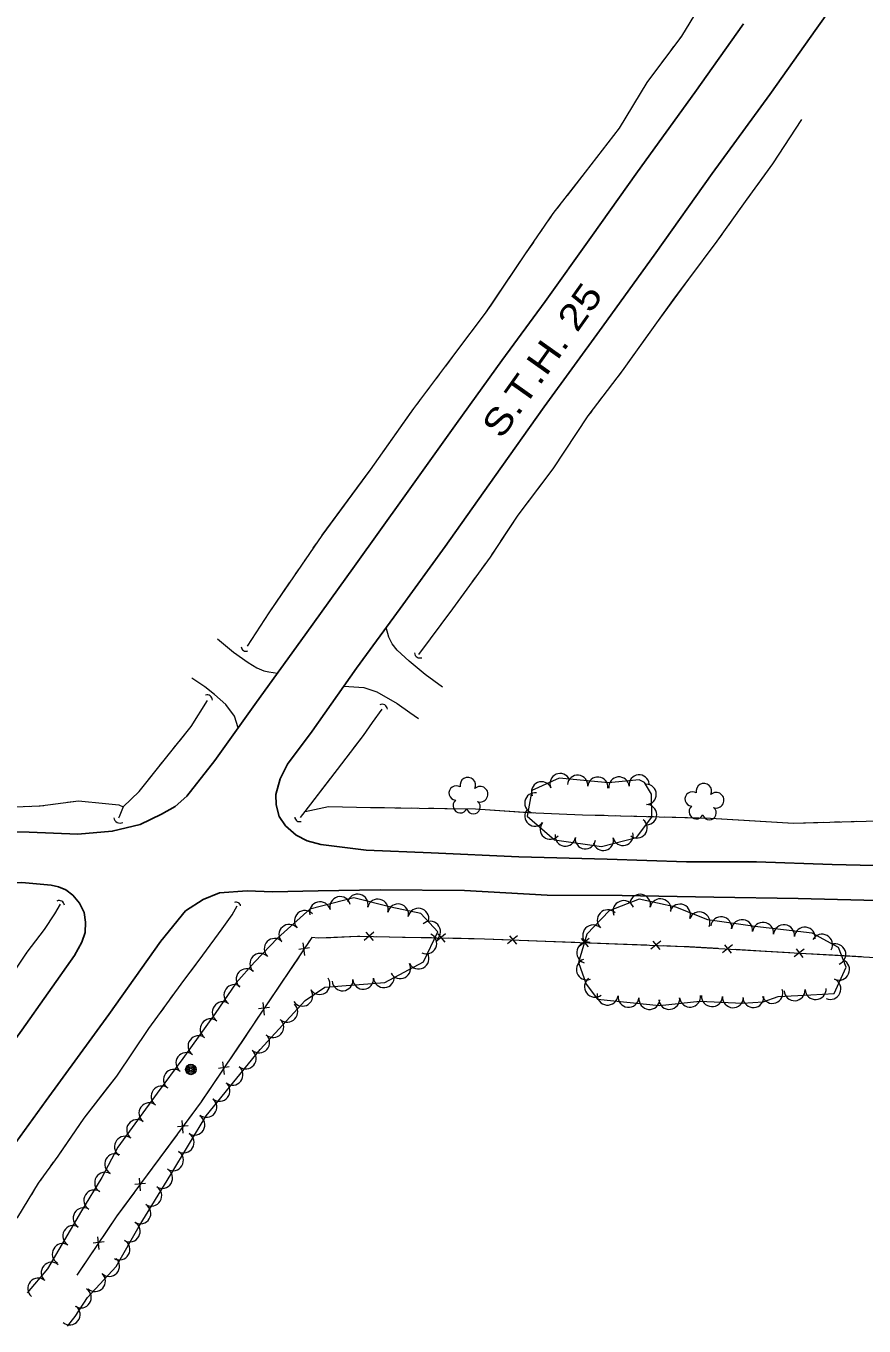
# Model space of a CAD drawing. Extents: x 298072 to 300359, y 47756 to 50122.
# Drawn here: x 299060 to 299380.3, y 48326.9 to 48823.7 of the extents above; entities that cross this region are included whole.
import ezdxf

# ---------------------------------------------------------------- set-up
doc = ezdxf.new("R2010")
doc.units = 0
doc.header["$LTSCALE"] = 2.4
doc.linetypes.add('LONG_DASHED', pattern=[7.5, 6, -1.5])
for name, color, linetype, lineweight in [('11', 7, 'Continuous', 25), ('14', 7, 'Continuous', 13), ('15', 7, 'Continuous', 13), ('17', 7, 'LONG_DASHED', 13), ('18', 7, 'Continuous', 13), ('19', 7, 'Continuous', 13)]:
    doc.layers.add(name, color=color, linetype=linetype, lineweight=lineweight)

msp = doc.modelspace()

# ---------------------------------------------------------------- linework, layer by layer
at = {"layer": '11'}
for points in [[(299159.9, 48541.54), (299169.315, 48554.227), (299186.27, 48578.226), (299202.993, 48601.032), (299220.126, 48624.785), (299239.084, 48651.357), (299258.045, 48678.115), (299280.157, 48708.592), (299300.706, 48737.003), (299322.267, 48767.276), (299344.231, 48797.56), (299362.207, 48822.854), (299379.626, 48847.266)], [(299040.651, 48515.988), (299061.171, 48515.642), (299079.772, 48514.891), (299092.916, 48515.978), (299103.646, 48518.533), (299111.803, 48522.431), (299117.044, 48525.433), (299121.494, 48529.393), (299132.182, 48543.024), (299148.033, 48565.259), (299166.727, 48590.963), (299185.573, 48617.31), (299204.756, 48644.113), (299224.578, 48671.815), (299241.848, 48695.801), (299258.384, 48718.46), (299275.868, 48742.919), (299293.681, 48768), (299315.556, 48798.256), (299334.267, 48824.557)], [(299159.9, 48541.54), (299157.116, 48536.015), (299155.509, 48530.063), (299155.644, 48525.997), (299156.743, 48521.651), (299159.162, 48518.027), (299163.236, 48514.452), (299167.446, 48512.314), (299172.654, 48510.945), (299189.998, 48508.773), (299214.809, 48507.751), (299248.337, 48506.161), (299282.112, 48505.341), (299312.382, 48504.318), (299339.159, 48504.234), (299368.13, 48503.278), (299410.735, 48502.254), (299439.997, 48501.987), (299472.691, 48501.745), (299499.707, 48501.466), (299530.639, 48500.816), (299559.37, 48500.568), (299584.941, 48499.652), (299594.667, 48499.415)], [(298856.43, 48502.098), (298886.422, 48502.837), (298921.67, 48501.855), (298960.034, 48500.114), (299004.015, 48497.993), (299038.664, 48495.79), (299058.368, 48496.338), (299069.567, 48495.309), (299072.437, 48494.733), (299075.152, 48493.629), (299077.868, 48491.528), (299080.463, 48488.49), (299082.145, 48484.904), (299082.73, 48481.177), (299082.533, 48477.203), (299081.364, 48473.612), (299078.474, 48468.424), (299058.337, 48439.986), (299037.794, 48411.569), (299021.737, 48389.305), (299009.962, 48373.031)], [(299028.794, 48358.922), (299046.078, 48383.296), (299067.642, 48413.073), (299091.651, 48445.959), (299111.467, 48473.957), (299120.982, 48485.542), (299127.672, 48489.835), (299133.956, 48492.451), (299144.552, 48493.154), (299154.25, 48492.804), (299171.68, 48493.142), (299195.394, 48493.553), (299227.514, 48493.295), (299259.174, 48491.522), (299287.804, 48491.45), (299322.814, 48490.828), (299355.076, 48490.314), (299380.259, 48489.565), (299413.071, 48489.188)]]:
    msp.add_lwpolyline(points, dxfattribs=at)
at = {"layer": '14'}
for centre, radius in [((299122.993, 48424.924), 2.018), ((299122.981, 48424.929), 1.518), ((299123.017, 48424.911), 1.008), ((299123.011, 48424.92), 0.502)]:
    msp.add_circle(centre, radius, dxfattribs=at)
at = {"layer": '15'}
for p, q in [((299192.966, 48477.353), (299189.243, 48474.242)), ((299192.732, 48474.17), (299190.046, 48477.347)), ((299165.783, 48473.273), (299166.382, 48468.458)), ((299203.867, 48475.416), (299194.072, 48475.619)), ((299215.005, 48475.185), (299203.867, 48475.416)), ((299220.375, 48476.785), (299216.652, 48473.674)), ((299220.142, 48473.602), (299217.456, 48476.779)), ((299231.277, 48474.848), (299221.481, 48475.051)), ((299247.808, 48475.998), (299244.031, 48472.953)), ((299247.519, 48472.819), (299244.889, 48476.042)), ((299258.674, 48473.87), (299248.883, 48474.244)), ((299269.806, 48473.445), (299258.674, 48473.87)), ((299275.203, 48474.951), (299271.426, 48471.906)), ((299274.914, 48471.772), (299272.284, 48474.996)), ((299286.069, 48472.823), (299276.278, 48473.197)), ((299297.201, 48472.398), (299286.069, 48472.823)), ((299302.598, 48473.904), (299298.822, 48470.859)), ((299302.309, 48470.726), (299299.679, 48473.949)), ((299330.01, 48472.496), (299326.174, 48469.526)), ((299329.659, 48469.324), (299327.092, 48472.598)), ((299164.22, 48467.892), (299157.994, 48458.654)), ((299168.332, 48471.353), (299164.207, 48470.815)), ((299324.584, 48471.096), (299313.463, 48471.74)), ((299340.832, 48470.156), (299331.05, 48470.722)), ((299351.954, 48469.512), (299340.832, 48470.156)), ((299357.379, 48470.912), (299353.544, 48467.942)), ((299357.028, 48467.74), (299354.462, 48471.014)), ((299368.202, 48468.572), (299358.42, 48469.138)), ((299379.323, 48467.928), (299368.202, 48468.572)), ((299157.994, 48458.654), (299152.519, 48450.528)), ((299153.011, 48448.618), (299148.886, 48448.08)), ((299150.462, 48450.538), (299151.061, 48445.724)), ((299148.899, 48445.157), (299142.673, 48435.919)), ((299142.673, 48435.919), (299137.198, 48427.794)), ((299135.141, 48427.804), (299135.74, 48422.989)), ((299137.69, 48425.884), (299133.565, 48425.346)), ((299133.578, 48422.423), (299127.352, 48413.185)), ((299121.967, 48403.355), (299117.822, 48402.997)), ((299119.502, 48405.384), (299119.892, 48400.548)), ((299117.708, 48400.076), (299111.089, 48391.115)), ((299111.089, 48391.115), (299105.267, 48383.235)), ((299103.212, 48383.334), (299103.602, 48378.498)), ((299101.418, 48378.025), (299094.798, 48369.065)), ((299105.676, 48381.305), (299101.531, 48380.946)), ((299089.803, 48359.037), (299085.678, 48358.502)), ((299087.255, 48360.959), (299087.85, 48356.144)), ((299085.688, 48355.579), (299079.456, 48346.345))]:
    msp.add_line(p, q, dxfattribs=at)
for points in [[(299395.571, 48466.988), (299311.592, 48471.848), (299235.229, 48474.766), (299186.719, 48475.771), (299171.675, 48475.059), (299169.284, 48475.406), (299126.928, 48412.555), (299094.716, 48368.954), (299079.456, 48346.345)], [(299176.467, 48475.286), (299171.675, 48475.059), (299169.284, 48475.406), (299167.84, 48473.263)], [(299187.596, 48475.753), (299186.719, 48475.771), (299176.467, 48475.286)], [(299242.411, 48474.492), (299235.229, 48474.766), (299231.277, 48474.848)], [(299313.463, 48471.74), (299311.592, 48471.848), (299303.674, 48472.151)], [(299127.352, 48413.185), (299126.928, 48412.555), (299121.557, 48405.285)], [(299094.798, 48369.065), (299094.716, 48368.954), (299089.312, 48360.947)]]:
    msp.add_lwpolyline(points, dxfattribs=at)
for centre, radius, start, end in [((299144.134, 48586.606), 1.876, 184.1637, 290.40327), ((299210.562, 48584.246), 2.092, 183.95389, 290.19346), ((299129.197, 48566.037), 2.046, 0.76582, 107.00538), ((299196.062, 48562.335), 2.127, 8.59007, 114.82964), ((299095.918, 48521.516), 2.445, 190.58294, 296.8225), ((299164.504, 48521.45), 1.825, 183.7445, 289.98407), ((299072.647, 48487.387), 2.095, 8.09709, 114.33665), ((299140.39, 48487.219), 1.627, 7.79274, 114.03231)]:
    msp.add_arc(centre, radius, start, end, dxfattribs=at)
at = {"layer": '17'}
for points in [[(299219.116, 48571.015), (299212.518, 48575.834), (299206.424, 48580.906), (299201.79, 48585.159), (299199.885, 48587.62), (299198.604, 48590.08), (299197.672, 48593.775)], [(299133.119, 48589.509), (299139.311, 48584.442), (299144.858, 48580.479), (299148.204, 48578.47), (299150.908, 48577.301), (299152.746, 48576.932), (299156.137, 48576.402)], [(299141.099, 48555.532), (299139.61, 48559.903), (299136.324, 48564.36), (299132.014, 48568.274), (299128.347, 48571.126), (299123.408, 48574.45)], [(299181.427, 48571.371), (299189.105, 48570.879), (299194.064, 48569.185), (299201.82, 48564.793), (299206.717, 48561.367), (299210.011, 48559.055)]]:
    msp.add_lwpolyline(points, dxfattribs=at)
at = {"layer": '18'}
for points in [[(299282.566, 48534.477), (299263.708, 48536.197), (299253.272, 48531.579), (299251.49, 48521.681), (299262.008, 48512.675), (299279.9, 48510.172), (299293.268, 48513.624), (299299.235, 48521.33), (299299.044, 48530.132), (299296.374, 48534.579), (299294.312, 48535.664)], [(299302.043, 48449.378), (299317.569, 48451.066), (299333.857, 48450.26), (299341.674, 48450.736), (299347.511, 48452.77), (299360.005, 48453.458), (299368.909, 48453.948), (299373.444, 48464.01), (299370.573, 48471.493), (299360.506, 48477.058), (299338.564, 48479.616), (299320.595, 48482.046), (299308.331, 48487.001), (299294.354, 48490.065), (299282.854, 48485.5), (299274.306, 48476.571), (299271.193, 48465.803), (299274.109, 48457.508), (299278.375, 48451.82)]]:
    msp.add_lwpolyline(points, close=True, dxfattribs=at)
msp.add_lwpolyline([(299075.868, 48326.889), (299078.715, 48330.487), (299083.47, 48337.821), (299094.439, 48349.661), (299103.168, 48365.018), (299115.294, 48384.758), (299128.814, 48407.143), (299149.428, 48432.491), (299166.683, 48451.318), (299174.152, 48456.349), (299197.082, 48458.109), (299211.942, 48465.998), (299217.362, 48477.464), (299210.935, 48484.466), (299199.381, 48486.922), (299185.319, 48490.47), (299168.428, 48486.194), (299156.181, 48475.214), (299147.271, 48465.98), (299140.245, 48458.02), (299132.32, 48446.358), (299119.928, 48429.108), (299110.122, 48415.851), (299095.071, 48395.266), (299088.949, 48383.579), (299081.159, 48370.859), (299068.236, 48348.697), (299060.478, 48339.538)], dxfattribs=at)
for centre, radius, start, end in [((299264.127, 48534.165), 3.875, 23.87737, 203.86205), ((299270.805, 48533.513), 3.875, 354.79625, 174.78093), ((299294.335, 48533.628), 3.875, 5.77814, 185.76281), ((299224.418, 48530.576), 2.777, 55.8556, 263.62859), ((299228.861, 48533.6), 2.974, 332.88471, 194.11859), ((299233.559, 48530.107), 2.975, 250.53553, 133.5088), ((299257.04, 48531.028), 3.875, 23.87737, 203.86205), ((299278.522, 48532.809), 3.875, 354.79625, 174.78093), ((299286.625, 48532.848), 3.875, 5.77814, 185.76281), ((299297.017, 48530.037), 3.875, 271.25076, 91.23544), ((299319.068, 48531.308), 2.974, 332.88471, 194.11859), ((299225.991, 48525.765), 2.783, 132.53262, 333.54366), ((299231.002, 48525.212), 2.611, 195.24076, 53.17337), ((299254.466, 48526.765), 3.875, 79.80167, 259.78635), ((299314.625, 48528.284), 2.777, 55.8556, 263.62859), ((299323.766, 48527.815), 2.975, 250.53553, 133.5088), ((299254.495, 48521.778), 3.875, 139.43599, 319.42067), ((299297.185, 48522.289), 3.875, 271.25076, 91.23544), ((299316.198, 48523.473), 2.783, 132.53262, 333.54366), ((299321.209, 48522.92), 2.611, 195.24076, 53.17337), ((299260.382, 48516.738), 3.875, 139.43599, 319.42067), ((299293.5, 48517.237), 3.875, 232.25591, 52.24059), ((299266.124, 48514.147), 3.875, 172.04396, 352.02863), ((299273.799, 48513.074), 3.875, 172.04396, 352.02863), ((299280.657, 48512.462), 3.875, 194.48677, 14.47145), ((299288.161, 48514.4), 3.875, 194.48677, 14.47145), ((299172.355, 48485.045), 3.969, 14.21378, 194.19846), ((299180.049, 48486.993), 3.969, 14.21378, 194.19846), ((299186.726, 48487.973), 3.969, 345.84685, 165.83153), ((299194.421, 48486.031), 3.969, 345.84685, 165.83153), ((299202.222, 48484.194), 3.969, 348.00709, 167.99176), ((299288.378, 48485.428), 4.022, 21.65859, 201.64326), ((299294.664, 48487.842), 4.022, 347.64303, 167.6277), ((299302.521, 48486.119), 4.022, 347.64303, 167.6277), ((299309.914, 48484.091), 4.022, 338.00757, 157.99225), ((299166.529, 48481.702), 3.969, 41.88535, 221.87003), ((299209.986, 48482.544), 3.969, 348.00709, 167.99176), ((299282.344, 48481.923), 4.022, 46.25652, 226.24119), ((299317.372, 48481.077), 4.022, 338.00757, 157.99225), ((299325.683, 48479.233), 4.022, 352.30611, 172.29079), ((299160.62, 48476.404), 3.969, 41.88535, 221.87003), ((299214.414, 48477.604), 3.969, 312.55588, 132.54056), ((299276.781, 48476.112), 4.022, 46.25652, 226.24119), ((299333.654, 48478.155), 4.022, 352.30611, 172.29079), ((299341.672, 48477.134), 4.022, 353.35813, 173.34281), ((299349.662, 48476.203), 4.022, 353.35813, 173.34281), ((299357.652, 48475.271), 4.022, 353.35813, 173.34281), ((299155.011, 48471.01), 3.969, 46.03069, 226.01537), ((299212.988, 48473.072), 3.969, 244.70747, 64.69215), ((299274.478, 48469.585), 4.022, 73.88322, 253.8679), ((299364.227, 48472.595), 4.022, 331.07401, 151.05869), ((299369.308, 48468.912), 4.022, 290.99795, 110.98263), ((299149.5, 48465.298), 3.969, 46.03069, 226.01537), ((299210.001, 48467.319), 3.969, 207.97097, 27.95565), ((299144.275, 48459.447), 3.969, 48.574, 228.55868), ((299202.991, 48463.598), 3.969, 207.97097, 27.95565), ((299274.339, 48463.201), 4.022, 109.37613, 289.36081), ((299370.708, 48463.064), 4.022, 245.74631, 65.73098), ((299172.197, 48457.537), 3.969, 213.97124, 33.95592), ((299180.951, 48458.954), 3.969, 184.39681, 4.38149), ((299188.865, 48459.562), 3.969, 184.39681, 4.38149), ((299196.779, 48460.169), 3.969, 184.39681, 4.38149), ((299277.443, 48456.571), 4.022, 126.87756, 306.86224), ((299367.403, 48455.731), 4.022, 245.74631, 65.73098), ((299139.603, 48453.379), 3.969, 55.8093, 235.79398), ((299165.614, 48453.103), 3.969, 213.97124, 33.95592), ((299282.256, 48453.536), 4.022, 174.11688, 354.10156), ((299290.257, 48452.711), 4.022, 174.11688, 354.10156), ((299313.811, 48452.775), 4.022, 186.21254, 6.19721), ((299322.161, 48452.947), 4.022, 177.17473, 357.15941), ((299330.195, 48452.549), 4.022, 177.17473, 357.15941), ((299337.994, 48452.621), 4.022, 183.49227, 3.47694), ((299345.217, 48454.2), 4.022, 199.21941, 19.20408), ((299353.734, 48455.221), 4.022, 183.15955, 3.14423), ((299361.766, 48455.663), 4.022, 183.15755, 3.14223), ((299135.142, 48446.814), 3.969, 55.8093, 235.79398), ((299159.863, 48446.952), 3.969, 227.50231, 47.48699), ((299298.259, 48451.885), 4.022, 174.11688, 354.10156), ((299305.814, 48451.906), 4.022, 186.21254, 6.19721), ((299130.522, 48440.294), 3.969, 54.31507, 234.29975), ((299154.501, 48441.1), 3.969, 227.50231, 47.48699), ((299125.891, 48433.848), 3.969, 54.31507, 234.29975), ((299149.138, 48435.249), 3.969, 227.50231, 47.48699), ((299121.236, 48427.384), 3.969, 53.51789, 233.50257), ((299143.968, 48429.069), 3.969, 230.88828, 50.87296), ((299116.516, 48421.003), 3.969, 53.51789, 233.50257), ((299138.96, 48422.912), 3.969, 230.88828, 50.87296), ((299111.796, 48414.622), 3.969, 53.51789, 233.50257), ((299133.952, 48416.754), 3.969, 230.88828, 50.87296), ((299128.945, 48410.596), 3.969, 230.88828, 50.87296), ((299107.119, 48408.224), 3.969, 53.83476, 233.81943), ((299102.434, 48401.817), 3.969, 53.83476, 233.81943), ((299124.36, 48403.787), 3.969, 238.8767, 58.86138), ((299097.749, 48395.41), 3.969, 53.83476, 233.81943), ((299120.257, 48396.993), 3.969, 238.8767, 58.86138), ((299116.153, 48390.199), 3.969, 238.8767, 58.86138), ((299094.016, 48388.775), 3.969, 62.36077, 242.34545), ((299090.207, 48381.655), 3.969, 58.52347, 238.50814), ((299112.04, 48383.429), 3.969, 238.44585, 58.43053), ((299086.062, 48374.887), 3.969, 58.52347, 238.50814), ((299107.886, 48376.666), 3.969, 238.44585, 58.43053), ((299103.731, 48369.903), 3.969, 238.44585, 58.43053), ((299081.975, 48368.135), 3.969, 59.76055, 239.74523), ((299077.977, 48361.279), 3.969, 59.76055, 239.74523), ((299099.643, 48363.02), 3.969, 240.39353, 60.37821), ((299073.979, 48354.422), 3.969, 59.76055, 239.74523), ((299095.721, 48356.119), 3.969, 240.39353, 60.37821), ((299069.758, 48347.28), 3.969, 49.74187, 229.72655), ((299091.767, 48349.834), 3.969, 227.19454, 47.17921), ((299064.628, 48341.223), 3.969, 49.74187, 229.72655), ((299086.373, 48344.011), 3.969, 227.19454, 47.17921), ((299080.953, 48337.757), 3.969, 237.0503, 57.03497), ((299076.702, 48331.29), 3.969, 231.65405, 51.63873)]:
    msp.add_arc(centre, radius, start, end, dxfattribs=at)
at = {"layer": '19'}
for p, q in [((299306.427, 48814.232), (299307.624, 48815.836)), ((299302.834, 48809.418), (299304.032, 48811.022)), ((299263.191, 48754.201), (299264.423, 48755.779)), ((299335.749, 48757.698), (299336.977, 48759.397)), ((299259.658, 48749.348), (299260.787, 48751.001)), ((299332.106, 48752.574), (299333.32, 48754.282)), ((299256.271, 48744.388), (299257.4, 48746.041)), ((299328.465, 48747.448), (299329.679, 48749.156)), ((299286.454, 48689.902), (299287.722, 48691.571)), ((299216.835, 48688.93), (299218.039, 48690.53)), ((299282.649, 48684.897), (299283.917, 48686.566)), ((299213.225, 48684.127), (299214.429, 48685.728)), ((299278.845, 48679.892), (299280.113, 48681.561)), ((299209.615, 48679.325), (299210.819, 48680.926)), ((299173.189, 48629.061), (299190.415, 48652.434)), ((299169.79, 48624.107), (299170.922, 48625.759)), ((299238.011, 48621.538), (299239.167, 48623.285)), ((299166.394, 48619.15), (299167.526, 48620.803)), ((299234.351, 48616.426), (299235.583, 48618.122)), ((299162.998, 48614.194), (299164.13, 48615.846)), ((299230.656, 48611.338), (299231.888, 48613.034)), ((299116.17, 48547.41), (299116.99, 48548.416)), ((299111.301, 48541.334), (299112.104, 48542.353)), ((299180.291, 48541.225), (299181.076, 48542.255)), ((299182.647, 48544.316), (299183.432, 48545.346)), ((299177.931, 48538.136), (299178.72, 48539.165)), ((299059.542, 48525.431), (299061.36, 48525.502)), ((299070.409, 48526.317), (299072.212, 48526.553)), ((299201.177, 48524.943), (299203.277, 48524.91)), ((299207.477, 48524.845), (299209.577, 48524.812)), ((299213.776, 48524.752), (299215.876, 48524.723)), ((299285.109, 48521.957), (299287.208, 48521.9)), ((299291.407, 48521.787), (299293.506, 48521.73)), ((299297.705, 48521.617), (299299.804, 48521.561)), ((299369.037, 48519.53), (299371.136, 48519.587)), ((299375.334, 48519.702), (299377.433, 48519.759)), ((299115.26, 48451.984), (299116.514, 48453.711)), ((299111.498, 48446.803), (299112.752, 48448.53)), ((299069.306, 48387.78), (299070.546, 48389.516)), ((299065.586, 48382.571), (299066.826, 48384.307)), ((299062.153, 48377.169), (299063.271, 48378.987))]:
    msp.add_line(p, q, dxfattribs=at)
for points in [[(299144.641, 48586.74), (299152.882, 48599.428), (299173.116, 48628.962), (299191.661, 48654.124), (299208.21, 48677.455), (299224.321, 48698.888), (299235.663, 48713.988), (299250.95, 48736.596), (299261.449, 48751.97), (299273.799, 48767.788), (299286.864, 48784.687), (299297.387, 48802.119), (299310.613, 48819.841), (299323.396, 48840.828)], [(299310.019, 48819.046), (299310.613, 48819.841), (299311.138, 48820.703)], [(299284.684, 48781.867), (299286.864, 48784.687), (299297.387, 48802.119), (299300.439, 48806.208)], [(299210.169, 48583.479), (299223.072, 48600.893), (299237.47, 48620.721), (299248.058, 48636.717), (299261.433, 48654.401), (299274.89, 48674.69), (299287.929, 48691.843), (299301.037, 48710.29), (299313.26, 48726.955), (299324.209, 48741.456), (299335.604, 48757.498), (299345.409, 48771.061), (299356.467, 48787.939)], [(299339.432, 48762.793), (299345.409, 48771.061), (299356.467, 48787.939)], [(299266.887, 48758.935), (299273.799, 48767.788), (299284.684, 48781.867)], [(299237.732, 48717.048), (299250.95, 48736.596), (299254.013, 48741.081)], [(299307.902, 48719.649), (299313.26, 48726.955), (299324.209, 48741.456), (299326.038, 48744.03)], [(299220.445, 48693.732), (299224.321, 48698.888), (299235.663, 48713.988), (299237.732, 48717.048)], [(299290.159, 48694.981), (299301.037, 48710.29), (299307.902, 48719.649)], [(299190.415, 48652.434), (299191.661, 48654.124), (299207.246, 48676.096)], [(299259.2, 48651.448), (299261.433, 48654.401), (299274.89, 48674.69), (299276.308, 48676.556)], [(299241.481, 48626.78), (299248.058, 48636.717), (299259.2, 48651.448)], [(299144.641, 48586.74), (299152.882, 48599.428), (299160.734, 48610.89)], [(299210.169, 48583.479), (299223.072, 48600.893), (299228.193, 48607.946)], [(299097.133, 48525.348), (299103.248, 48531.126), (299113.755, 48544.445), (299123.112, 48555.931), (299129.323, 48565.886)], [(299118.63, 48550.429), (299123.112, 48555.931), (299129.323, 48565.886)], [(299164.9, 48521.19), (299168.819, 48526.251), (299179.025, 48539.563), (299188.964, 48552.606), (299192.464, 48557.541), (299196.049, 48562.594)], [(299185.003, 48547.407), (299188.964, 48552.606), (299192.464, 48557.541), (299196.049, 48562.594)], [(299113.711, 48544.39), (299113.755, 48544.445), (299114.53, 48545.397)], [(298811.934, 48539.27), (298819.663, 48539.989), (298842.165, 48538.9), (298875.536, 48535.803), (298909.762, 48532.409), (298943.635, 48530.51), (299012.386, 48526.339), (299045.94, 48524.905), (299065.344, 48525.656), (299080.022, 48527.572), (299090.397, 48526.576), (299095.491, 48526.071), (299097.133, 48525.348), (299095.618, 48521.498), (299095.393, 48520.904)], [(299097.133, 48525.348), (299103.248, 48531.126), (299109.694, 48539.297)], [(299164.9, 48521.19), (299168.819, 48526.251), (299176.354, 48536.08)], [(299075.82, 48527.023), (299080.022, 48527.572), (299090.397, 48526.576), (299095.491, 48526.071), (299097.133, 48525.348), (299095.618, 48521.498), (299095.393, 48520.904)], [(299064.995, 48525.642), (299065.344, 48525.656), (299066.801, 48525.846)], [(299166.722, 48523.543), (299175.59, 48525.392), (299191.65, 48525.091), (299210.302, 48524.801), (299231.809, 48524.499), (299251.912, 48523.17), (299272.658, 48522.293), (299321.653, 48520.971), (299353.351, 48519.101), (299381.13, 48519.86), (299407.725, 48520.302), (299441.775, 48521.005), (299471.109, 48520.671), (299494.512, 48520.454), (299512.897, 48518.811), (299531.721, 48516.069), (299551.196, 48514.892), (299564.849, 48513.838), (299575.809, 48513.667), (299580.812, 48513.45), (299585.946, 48513.319)], [(299166.722, 48523.543), (299175.59, 48525.392), (299191.65, 48525.091), (299196.978, 48525.008)], [(299220.076, 48524.664), (299231.809, 48524.499), (299250.484, 48523.264)], [(299250.484, 48523.264), (299251.912, 48523.17), (299272.658, 48522.293), (299280.91, 48522.07)], [(299304.003, 48521.447), (299321.653, 48520.971), (299334.425, 48520.218)], [(299334.425, 48520.218), (299353.351, 48519.101), (299364.838, 48519.415)], [(298999.485, 48383.835), (299014.86, 48402.028), (299029.947, 48423.832), (299041.41, 48441.4), (299051.257, 48455.959), (299060.455, 48469.714), (299067.08, 48478.42), (299071.029, 48484.414), (299073.099, 48488.131)], [(299042.661, 48348.046), (299049.896, 48360.957), (299056.841, 48368.536), (299064.79, 48381.456), (299072.216, 48391.854), (299082.226, 48406.304), (299094.63, 48422.381), (299106.961, 48440.554), (299119.285, 48457.527), (299127.615, 48468.6), (299134.966, 48478.728), (299138.814, 48483.98), (299140.713, 48487.491)], [(299060.033, 48469.083), (299060.455, 48469.714), (299067.08, 48478.42), (299071.029, 48484.414), (299073.099, 48488.131)], [(299122.864, 48462.285), (299127.615, 48468.6), (299134.966, 48478.728), (299138.814, 48483.98), (299140.713, 48487.491)], [(299119.022, 48457.165), (299119.285, 48457.527), (299120.299, 48458.875)], [(299091.247, 48417.997), (299094.63, 48422.381), (299106.961, 48440.554), (299108.99, 48443.349)], [(299073.01, 48393), (299082.226, 48406.304), (299091.247, 48417.997)]]:
    msp.add_lwpolyline(points, dxfattribs=at)

# ---------------------------------------------------------------- texts
at = {"layer": '11', "width": 1.2}
msp.add_text('S.T.H. 25', height=10, rotation=54.678, dxfattribs=at).set_placement((299241.728, 48665.466))

doc.saveas('drawing.dxf')
